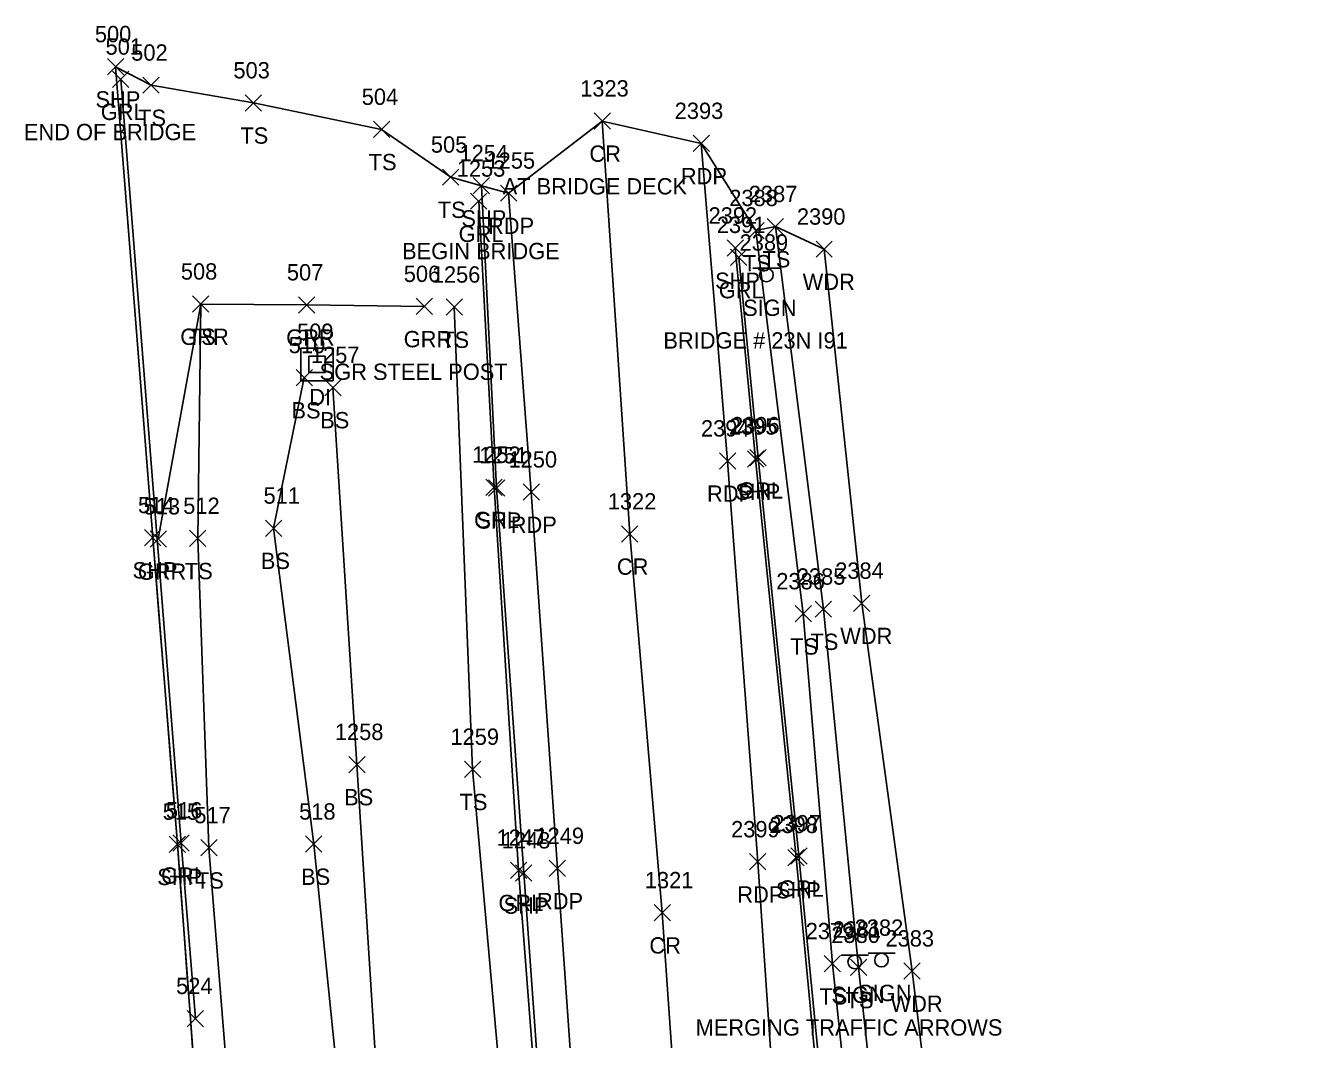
# Model space of a CAD drawing. Extents: x 1650221 to 1650634, y 244606 to 249996.
# Drawn here: x 1650220.8 to 1650378.2, y 247145.3 to 247269.5 of the extents above; entities that cross this region are included whole.
import ezdxf

# ---------------------------------------------------------------- set-up
doc = ezdxf.new("R2010")
doc.units = 0
for name, color, linetype in [('D_A', 7, 'Continuous'), ('D_I', 7, 'Continuous'), ('DS', 7, 'Continuous'), ('L_A', 7, 'Continuous'), ('L_I', 7, 'Continuous'), ('L_TIC', 7, 'Continuous'), ('LAWA', 7, 'Continuous'), ('LELB', 7, 'Continuous'), ('LSOGP', 7, 'Continuous'), ('P_A', 7, 'Continuous'), ('P_C', 7, 'Continuous'), ('P_I', 7, 'Continuous'), ('P_TIC', 7, 'Continuous'), ('PET', 7, 'Continuous'), ('PRC', 7, 'Continuous'), ('PSP', 7, 'Continuous'), ('R_A', 7, 'Continuous'), ('R_C', 7, 'Continuous'), ('R_I', 7, 'Continuous'), ('R_TIC', 7, 'Continuous'), ('RGR', 7, 'Continuous'), ('S_A', 7, 'Continuous'), ('S_C', 7, 'Continuous'), ('S_I', 7, 'Continuous'), ('SSGN', 7, 'Continuous')]:
    doc.layers.add(name, color=color, linetype=linetype)

msp = doc.modelspace()

# ---------------------------------------------------------------- linework, layer by layer
at = {"layer": 'DS'}
for p, q in [((1650254.51, 247229.97), (1650258.51, 247229.97)), ((1650254.51, 247225.97), (1650254.51, 247229.97)), ((1650258.51, 247229.97), (1650258.51, 247225.97)), ((1650255.51, 247226.97), (1650255.51, 247228.97)), ((1650255.51, 247228.97), (1650257.51, 247228.97)), ((1650256.52, 247227.97), (1650256.52, 247227.97)), ((1650256.52, 247227.97), (1650256.52, 247227.97)), ((1650257.51, 247228.97), (1650257.51, 247226.97)), ((1650257.51, 247226.97), (1650255.51, 247226.97)), ((1650258.51, 247225.97), (1650254.51, 247225.97))]:
    msp.add_line(p, q, dxfattribs=at)
at = {"layer": 'L_TIC'}
for points in [[(1650235.19, 247261.18), (1650237.19, 247263.18)], [(1650237.19, 247261.18), (1650235.19, 247263.18)], [(1650247.71, 247259.01), (1650249.71, 247261.01)], [(1650249.71, 247259.01), (1650247.71, 247261.01)], [(1650263.43, 247255.76), (1650265.43, 247257.76)], [(1650265.43, 247255.76), (1650263.43, 247257.76)], [(1650271.9, 247249.91), (1650273.9, 247251.91)], [(1650273.9, 247249.91), (1650271.9, 247251.91)], [(1650309.27, 247243.37), (1650311.27, 247245.37)], [(1650311.27, 247243.37), (1650309.27, 247245.37)], [(1650309.27, 247243.37), (1650311.27, 247245.37)], [(1650311.27, 247243.37), (1650309.27, 247245.37)], [(1650311.67, 247243.86), (1650313.67, 247245.86)], [(1650313.67, 247243.86), (1650311.67, 247245.86)], [(1650317.64, 247241.09), (1650319.64, 247243.09)], [(1650319.64, 247241.09), (1650317.64, 247243.09)], [(1650241.27, 247234.36), (1650243.27, 247236.36)], [(1650243.27, 247234.36), (1650241.27, 247236.36)], [(1650272.32, 247233.99), (1650274.32, 247235.99)], [(1650274.32, 247233.99), (1650272.32, 247235.99)], [(1650253.94, 247225.35), (1650255.94, 247227.35)], [(1650255.94, 247225.35), (1650253.94, 247227.35)], [(1650257.46, 247224.14), (1650259.46, 247226.14)], [(1650259.46, 247224.14), (1650257.46, 247226.14)], [(1650240.91, 247205.66), (1650242.91, 247207.66)], [(1650242.91, 247205.66), (1650240.91, 247207.66)], [(1650250.19, 247206.91), (1650252.19, 247208.91)], [(1650252.19, 247206.91), (1650250.19, 247208.91)], [(1650322.25, 247197.71), (1650324.25, 247199.71)], [(1650324.25, 247197.71), (1650322.25, 247199.71)], [(1650315.08, 247196.42), (1650317.08, 247198.42)], [(1650317.08, 247196.42), (1650315.08, 247198.42)], [(1650317.55, 247196.99), (1650319.55, 247198.99)], [(1650319.55, 247196.99), (1650317.55, 247198.99)], [(1650260.39, 247177.96), (1650262.39, 247179.96)], [(1650262.39, 247177.96), (1650260.39, 247179.96)], [(1650274.56, 247177.37), (1650276.56, 247179.37)], [(1650276.56, 247177.37), (1650274.56, 247179.37)], [(1650242.27, 247167.76), (1650244.27, 247169.76)], [(1650244.27, 247167.76), (1650242.27, 247169.76)], [(1650255.12, 247168.21), (1650257.12, 247170.21)], [(1650257.12, 247168.21), (1650255.12, 247170.21)], [(1650318.65, 247153.56), (1650320.65, 247155.56)], [(1650320.65, 247153.56), (1650318.65, 247155.56)], [(1650321.86, 247153.1), (1650323.86, 247155.1)], [(1650323.86, 247153.1), (1650321.86, 247155.1)], [(1650328.41, 247152.66), (1650330.41, 247154.66)], [(1650330.41, 247152.66), (1650328.41, 247154.66)]]:
    msp.add_lwpolyline(points, dxfattribs=at)
at = {"layer": 'LAWA'}
msp.add_lwpolyline([(1650378.2, 246794.91), (1650374.9, 246794.97), (1650368.73, 246802.01), (1650359.68, 246824.66), (1650349.32, 246871.74), (1650348.02, 246917.21), (1650345.5, 246965.53), (1650341.28, 247016.15), (1650338.12, 247059.96), (1650335.1, 247106.89), (1650329.41, 247153.66), (1650323.25, 247198.71), (1650318.64, 247242.09)], dxfattribs=at)
at = {"layer": 'LELB'}
for points in [[(1650236.19, 247262.18), (1650248.71, 247260.01), (1650264.43, 247256.76), (1650272.9, 247250.91)], [(1650338.12, 247059.96), (1650328.16, 247105.4), (1650322.86, 247154.1), (1650318.55, 247197.99), (1650312.67, 247244.86), (1650310.27, 247244.37)], [(1650352.21, 246793.58), (1650347.7, 246827.18), (1650344.12, 246870.96), (1650340.96, 246916.6), (1650336.85, 246965.3), (1650332.82, 247015.91), (1650329.05, 247059.02), (1650324.85, 247105.51), (1650319.65, 247154.56), (1650316.08, 247197.42), (1650310.27, 247244.37)], [(1650242.27, 247235.36), (1650241.91, 247206.66), (1650243.27, 247168.76), (1650246.51, 247128.17), (1650248.83, 247083.97), (1650252.85, 247030.65), (1650256.86, 246977.49), (1650260.95, 246918.52), (1650265.57, 246863.83), (1650269.89, 246812.16), (1650273.23, 246757.17), (1650276.03, 246723.56), (1650279.21, 246672.89), (1650281.34, 246632.54), (1650285.04, 246583.81), (1650287.41, 246538.25), (1650291.5, 246485.31), (1650295.53, 246435.79), (1650299.48, 246380.33), (1650302.27, 246339.43), (1650306.13, 246294.16), (1650309.79, 246242.03)], [(1650273.32, 247234.99), (1650275.56, 247178.37), (1650280.16, 247126.65), (1650283.32, 247073.18), (1650288.39, 247022.86), (1650291, 246971.3), (1650295.86, 246921.31), (1650299.12, 246867.86), (1650302.48, 246825.54), (1650302.49, 246790.4)], [(1650254.94, 247226.35), (1650251.19, 247207.91), (1650256.12, 247169.21), (1650259.77, 247133.43), (1650260.76, 247116.75), (1650264.32, 247083.63), (1650267.53, 247032.12), (1650271.47, 246976.78), (1650276.33, 246918.79), (1650279.06, 246862.8), (1650283.73, 246813.9), (1650289.01, 246756.82), (1650289.41, 246725.67), (1650289.28, 246672.86), (1650289.57, 246632.6), (1650292.55, 246585.88), (1650294.65, 246538.84), (1650297.54, 246482.61), (1650299.6, 246436.73), (1650304.05, 246378.94), (1650306.26, 246339.81), (1650313.05, 246293.73), (1650316.43, 246243)], [(1650258.46, 247225.14), (1650261.39, 247178.96), (1650264.81, 247125.04), (1650270.68, 247074.02), (1650274.2, 247020.9), (1650277.12, 246971.1), (1650282.14, 246919.24), (1650285.26, 246868.32), (1650288.53, 246824.34), (1650289.93, 246790.87)]]:
    msp.add_lwpolyline(points, dxfattribs=at)
at = {"layer": 'LSOGP'}
msp.add_lwpolyline([(1650335.1, 247106.89), (1650329.41, 247153.66), (1650323.25, 247198.71), (1650318.64, 247242.09), (1650312.67, 247244.86), (1650310.27, 247244.37), (1650303.59, 247255.04), (1650291.45, 247257.79), (1650279.98, 247248.95), (1650276.66, 247249.86), (1650272.9, 247250.91), (1650264.43, 247256.76), (1650248.71, 247260.01), (1650236.19, 247262.18), (1650231.83, 247264.44), (1650232.4, 247257.22), (1650232.97, 247250.01), (1650233.54, 247242.8), (1650234.1, 247235.59), (1650234.67, 247228.38), (1650235.24, 247221.17), (1650235.81, 247213.96), (1650236.38, 247206.75), (1650237.13, 247197.36), (1650237.89, 247187.97), (1650238.65, 247178.58), (1650239.4, 247169.19), (1650239.79, 247163.99), (1650240.18, 247158.78), (1650240.57, 247153.57), (1650240.96, 247148.37), (1650241.35, 247143.16)], dxfattribs=at)
at = {"layer": 'P_TIC'}
for points in [[(1650230.83, 247263.44), (1650232.83, 247265.44)], [(1650232.83, 247263.44), (1650230.83, 247265.44)], [(1650290.45, 247256.79), (1650292.45, 247258.79)], [(1650292.45, 247256.79), (1650290.45, 247258.79)], [(1650302.59, 247254.04), (1650304.59, 247256.04)], [(1650304.59, 247254.04), (1650302.59, 247256.04)], [(1650275.66, 247248.86), (1650277.66, 247250.86)], [(1650277.66, 247248.86), (1650275.66, 247250.86)], [(1650278.98, 247247.95), (1650280.98, 247249.95)], [(1650280.98, 247247.95), (1650278.98, 247249.95)], [(1650306.74, 247241.22), (1650308.74, 247243.22)], [(1650308.74, 247241.22), (1650306.74, 247243.22)], [(1650305.81, 247215.14), (1650307.81, 247217.14)], [(1650307.81, 247215.14), (1650305.81, 247217.14)], [(1650309.23, 247215.37), (1650311.23, 247217.37)], [(1650311.23, 247215.37), (1650309.23, 247217.37)], [(1650277.51, 247211.85), (1650279.51, 247213.85)], [(1650279.51, 247211.85), (1650277.51, 247213.85)], [(1650281.75, 247211.34), (1650283.75, 247213.34)], [(1650283.75, 247211.34), (1650281.75, 247213.34)], [(1650235.38, 247205.75), (1650237.38, 247207.75)], [(1650237.38, 247205.75), (1650235.38, 247207.75)], [(1650293.82, 247206.2), (1650295.82, 247208.2)], [(1650295.82, 247206.2), (1650293.82, 247208.2)], [(1650238.4, 247168.19), (1650240.4, 247170.19)], [(1650240.4, 247168.19), (1650238.4, 247170.19)], [(1650314.19, 247166.56), (1650316.19, 247168.56)], [(1650316.19, 247166.56), (1650314.19, 247168.56)], [(1650280.83, 247164.68), (1650282.83, 247166.68)], [(1650282.83, 247164.68), (1650280.83, 247166.68)], [(1650284.97, 247165.23), (1650286.97, 247167.23)], [(1650286.97, 247165.23), (1650284.97, 247167.23)], [(1650309.51, 247166.04), (1650311.51, 247168.04)], [(1650311.51, 247166.04), (1650309.51, 247168.04)], [(1650297.8, 247159.8), (1650299.8, 247161.8)], [(1650299.8, 247159.8), (1650297.8, 247161.8)]]:
    msp.add_lwpolyline(points, dxfattribs=at)
at = {"layer": 'PET'}
for points in [[(1650303.59, 247255.04), (1650306.81, 247216.14), (1650310.51, 247167.04), (1650313.87, 247117.51), (1650317.79, 247067.14), (1650321.46, 247013.25), (1650325.74, 246955.86), (1650329.2, 246907.19), (1650332.99, 246853.31), (1650336.64, 246798.8), (1650340.79, 246743.67), (1650343.55, 246701.32), (1650346.09, 246667.41)], [(1650353.63, 246221.52), (1650350.67, 246260.72), (1650347.78, 246301.59), (1650344.6, 246348.96), (1650342.99, 246369.43), (1650339.44, 246417.63), (1650336.53, 246459.1), (1650332.81, 246507), (1650329.1, 246556.8), (1650325.84, 246602.52), (1650321.75, 246661.01), (1650317.87, 246717.27), (1650314.55, 246761.47), (1650311.27, 246802.48), (1650308.51, 246843.59), (1650304.95, 246897.23), (1650300.96, 246950.35), (1650297.4, 247001.83), (1650293.63, 247056.22), (1650290.13, 247106.77), (1650285.97, 247166.23), (1650282.75, 247212.34), (1650279.98, 247248.95)]]:
    msp.add_lwpolyline(points, dxfattribs=at)
at = {"layer": 'PRC'}
msp.add_lwpolyline([(1650365.1, 246222.23), (1650362.04, 246265.67), (1650358.21, 246317.53), (1650354.88, 246368.98), (1650350.4, 246428.86), (1650346.57, 246483.13), (1650341.97, 246537.02), (1650338.57, 246591.04), (1650334.55, 246647.32), (1650330.72, 246698.07), (1650326.82, 246753.45), (1650322.93, 246808.73), (1650318.78, 246866.3), (1650315.63, 246915.25), (1650311.69, 246971.18), (1650308.09, 247021.19), (1650305.21, 247068.94), (1650301.6, 247120.36), (1650298.8, 247160.8), (1650294.82, 247207.2), (1650291.45, 247257.79)], dxfattribs=at)
at = {"layer": 'PSP'}
for points in [[(1650231.83, 247264.44), (1650236.38, 247206.75), (1650239.4, 247169.19), (1650242.51, 247127.54), (1650245.5, 247084.02), (1650249.81, 247030.22), (1650253.62, 246978.01), (1650257.98, 246918.58), (1650261.69, 246863.47), (1650265.43, 246811.71), (1650269.36, 246757.46), (1650271.77, 246723.3), (1650275.43, 246673.04), (1650278.75, 246632.2), (1650282.06, 246584.21), (1650285.45, 246538.51), (1650289.06, 246485.48), (1650292.63, 246435.74), (1650296.7, 246380.37), (1650299.48, 246339.42), (1650302.95, 246294.11), (1650306.82, 246242.11)], [(1650349.68, 246222.04), (1650346.67, 246260.34), (1650343.46, 246301.15), (1650340.56, 246349.22), (1650338.99, 246369.3), (1650335.68, 246417.66), (1650332.87, 246458.75), (1650329.36, 246506.58), (1650325.51, 246556.6), (1650322.14, 246602.26), (1650317.67, 246660.67), (1650313.65, 246716.62), (1650310.76, 246760.87), (1650307.66, 246803.03), (1650304.71, 246843.75), (1650300.95, 246897.67), (1650297.16, 246949.75), (1650293.72, 247001.93), (1650289.97, 247055.55), (1650286.03, 247107.65), (1650281.83, 247165.68), (1650278.51, 247212.85), (1650276.66, 247249.86)], [(1650307.74, 247242.22), (1650310.23, 247216.37), (1650315.19, 247167.56), (1650319.94, 247117.42), (1650324.85, 247068), (1650329.68, 247013.47), (1650333.89, 246957.27), (1650337.47, 246907.25), (1650341.57, 246853.3), (1650345.82, 246798.32), (1650349.51, 246744.26), (1650352.38, 246701.38), (1650355.13, 246668.21)]]:
    msp.add_lwpolyline(points, dxfattribs=at)
at = {"layer": 'R_TIC'}
for points in [[(1650231.47, 247261.91), (1650233.47, 247263.91)], [(1650233.47, 247261.91), (1650231.47, 247263.91)], [(1650275.32, 247246.97), (1650277.32, 247248.97)], [(1650277.32, 247246.97), (1650275.32, 247248.97)], [(1650307.18, 247240.07), (1650309.18, 247242.07)], [(1650309.18, 247240.07), (1650307.18, 247242.07)], [(1650241.27, 247234.36), (1650243.27, 247236.36)], [(1650243.27, 247234.36), (1650241.27, 247236.36)], [(1650254.26, 247234.26), (1650256.26, 247236.26)], [(1650256.26, 247234.26), (1650254.26, 247236.26)], [(1650268.64, 247234.07), (1650270.64, 247236.07)], [(1650270.64, 247234.07), (1650268.64, 247236.07)], [(1650309.55, 247215.53), (1650311.55, 247217.53)], [(1650311.55, 247215.53), (1650309.55, 247217.53)], [(1650277.21, 247211.92), (1650279.21, 247213.92)], [(1650279.21, 247211.92), (1650277.21, 247213.92)], [(1650236.07, 247205.59), (1650238.07, 247207.59)], [(1650238.07, 247205.59), (1650236.07, 247207.59)], [(1650238.86, 247168.36), (1650240.86, 247170.36)], [(1650240.86, 247168.36), (1650238.86, 247170.36)], [(1650314.55, 247166.77), (1650316.55, 247168.77)], [(1650316.55, 247166.77), (1650314.55, 247168.77)], [(1650280.2, 247165), (1650282.2, 247167)], [(1650282.2, 247165), (1650280.2, 247167)], [(1650240.61, 247146.84), (1650242.61, 247148.84)], [(1650242.61, 247146.84), (1650240.61, 247148.84)]]:
    msp.add_lwpolyline(points, dxfattribs=at)
at = {"layer": 'RGR'}
for points in [[(1650232.47, 247262.91), (1650239.86, 247169.36), (1650241.61, 247147.84)], [(1650306.3, 246761.34), (1650307.52, 246782.05), (1650307.39, 246800.41), (1650304.06, 246843.7), (1650300.5, 246897.69), (1650296.68, 246949.72), (1650293.23, 247001.96), (1650289.46, 247055.48), (1650285.68, 247107.62), (1650281.2, 247166), (1650278.21, 247212.92), (1650276.32, 247247.97)], [(1650308.18, 247241.07), (1650310.55, 247216.53), (1650315.55, 247167.77), (1650320.43, 247117.51), (1650325.42, 247068.18), (1650330.46, 247013.43), (1650334.74, 246957.48), (1650338.49, 246907.23), (1650342.31, 246853.82), (1650346.19, 246798.3), (1650349.87, 246744.52), (1650353.37, 246701.53), (1650355.68, 246682.24), (1650357.83, 246668.94)], [(1650269.64, 247235.07), (1650255.26, 247235.26), (1650242.27, 247235.36), (1650237.07, 247206.59)]]:
    msp.add_lwpolyline(points, dxfattribs=at)
at = {"layer": 'SSGN'}
for p, q in [((1650309.92, 247239.76), (1650313.26, 247239.76)), ((1650311.57, 247238.93), (1650311.57, 247238.93)), ((1650320.73, 247155.61), (1650324.07, 247155.61)), ((1650324.02, 247155.84), (1650327.35, 247155.84)), ((1650322.38, 247154.77), (1650322.38, 247154.77)), ((1650325.66, 247155), (1650325.66, 247155))]:
    msp.add_line(p, q, dxfattribs=at)
for centre in [(1650311.57, 247238.93), (1650322.38, 247154.77), (1650325.66, 247155)]:
    msp.add_circle(centre, 0.833, dxfattribs=at)

# ---------------------------------------------------------------- texts
at = {"layer": 'D_A'}
msp.add_text('DI', height=2, dxfattribs=at).set_placement((1650255.57, 247222.97))
at = {"layer": 'D_I'}
msp.add_text('509', height=2, dxfattribs=at).set_placement((1650254.07, 247230.97))
at = {"layer": 'L_A'}
for s, p in [('TS', (1650234.6, 247257.18)), ('TS', (1650247.12, 247255.01)), ('TS', (1650262.84, 247251.76)), ('TS', (1650271.31, 247245.91)), ('TS', (1650308.68, 247239.37)), ('TS', (1650308.68, 247239.37)), ('TS', (1650311.08, 247239.86)), ('WDR', (1650316.01, 247237.09)), ('TS', (1650240.68, 247230.36)), ('TS', (1650271.73, 247229.99)), ('BS', (1650253.38, 247221.35)), ('BS', (1650256.9, 247220.14)), ('BS', (1650249.63, 247202.91)), ('TS', (1650240.32, 247201.66)), ('TS', (1650316.96, 247192.99)), ('WDR', (1650320.61, 247193.71)), ('TS', (1650314.49, 247192.42)), ('BS', (1650259.83, 247173.96)), ('TS', (1650273.97, 247173.37)), ('TS', (1650241.68, 247163.76)), ('BS', (1650254.56, 247164.21)), ('TS', (1650318.06, 247149.56)), ('TS', (1650321.27, 247149.1)), ('WDR', (1650326.77, 247148.66))]:
    msp.add_text(s, height=2, dxfattribs=at).set_placement(p)
at = {"layer": 'L_I'}
for s, p in [('502', (1650233.75, 247265.18)), ('503', (1650246.27, 247263.01)), ('504', (1650261.99, 247259.76)), ('505', (1650270.46, 247253.91)), ('2388', (1650307.01, 247247.37)), ('2388', (1650307.01, 247247.37)), ('2387', (1650309.41, 247247.86)), ('2390', (1650315.3, 247245.09)), ('508', (1650239.83, 247238.36)), ('1256', (1650270.57, 247237.99)), ('510', (1650253.05, 247229.35)), ('1257', (1650255.76, 247228.14)), ('511', (1650249.96, 247210.91)), ('512', (1650240.12, 247209.66)), ('2385', (1650315.29, 247200.99)), ('2384', (1650319.99, 247201.71)), ('2386', (1650312.77, 247200.42)), ('1258', (1650258.7, 247181.96)), ('1259', (1650272.86, 247181.37)), ('517', (1650241.48, 247171.76)), ('518', (1650254.32, 247172.21)), ('2379', (1650316.38, 247157.56)), ('2380', (1650319.52, 247157.1)), ('2383', (1650326.15, 247156.66))]:
    msp.add_text(s, height=2, dxfattribs=at).set_placement(p)
at = {"layer": 'P_A'}
for s, p in [('SHP', (1650229.37, 247259.44)), ('CR', (1650289.88, 247252.79)), ('RDP', (1650301.08, 247250.04)), ('SHP', (1650274.2, 247244.86)), ('RDP', (1650277.46, 247243.95)), ('SHP', (1650305.28, 247237.22)), ('RDP', (1650304.29, 247211.14)), ('SHP', (1650307.76, 247211.37)), ('SHP', (1650276.04, 247207.85)), ('RDP', (1650280.24, 247207.34)), ('SHP', (1650233.91, 247201.75)), ('CR', (1650293.25, 247202.2)), ('SHP', (1650236.94, 247164.19)), ('RDP', (1650308, 247162.04)), ('SHP', (1650312.72, 247162.56)), ('SHP', (1650279.37, 247160.68)), ('RDP', (1650283.46, 247161.23)), ('CR', (1650297.23, 247155.8))]:
    msp.add_text(s, height=2, dxfattribs=at).set_placement(p)
at = {"layer": 'P_C'}
for s, p in [('END OF BRIDGE', (1650220.6, 247255.44)), ('AT BRIDGE DECK', (1650279.26, 247248.79)), ('BEGIN BRIDGE', (1650266.93, 247240.86))]:
    msp.add_text(s, height=2, dxfattribs=at).set_placement(p)
at = {"layer": 'P_I'}
for s, p in [('500', (1650229.3, 247267.44)), ('1323', (1650288.75, 247260.79)), ('2393', (1650300.33, 247258.04)), ('1254', (1650273.97, 247252.86)), ('1255', (1650277.28, 247251.95)), ('2392', (1650304.48, 247245.22)), ('2394', (1650303.55, 247219.14)), ('2395', (1650306.97, 247219.37)), ('1251', (1650276.38, 247215.85)), ('1250', (1650279.97, 247215.34)), ('1322', (1650292.13, 247210.2)), ('514', (1650234.58, 247209.75)), ('515', (1650237.61, 247172.19)), ('2399', (1650307.24, 247170.04)), ('2398', (1650311.93, 247170.56)), ('1248', (1650279.14, 247168.68)), ('1249', (1650283.27, 247169.23)), ('1321', (1650296.67, 247163.8))]:
    msp.add_text(s, height=2, dxfattribs=at).set_placement(p)
at = {"layer": 'R_A'}
for s, p in [('GRL', (1650230.02, 247257.91)), ('GRL', (1650273.86, 247242.97)), ('GRL', (1650305.73, 247236.07)), ('GRR', (1650239.76, 247230.36)), ('GRR', (1650252.74, 247230.26)), ('GRR', (1650267.13, 247230.07)), ('GRL', (1650308.1, 247211.53)), ('GRL', (1650275.75, 247207.92)), ('GRR', (1650234.55, 247201.59)), ('GRL', (1650237.4, 247164.36)), ('GRL', (1650313.09, 247162.77)), ('GRL', (1650278.74, 247161))]:
    msp.add_text(s, height=2, dxfattribs=at).set_placement(p)
at = {"layer": 'R_C'}
msp.add_text('SGR STEEL POST', height=2, dxfattribs=at).set_placement((1650256.83, 247226.07))
at = {"layer": 'R_I'}
for s, p in [('501', (1650230.6, 247265.91)), ('1253', (1650273.63, 247250.97)), ('2391', (1650305.49, 247244.07)), ('508', (1650239.83, 247238.36)), ('507', (1650252.82, 247238.26)), ('506', (1650267.14, 247238.07)), ('2396', (1650307.24, 247219.53)), ('1252', (1650275.51, 247215.92)), ('513', (1650235.27, 247209.59)), ('516', (1650238, 247172.36)), ('2397', (1650312.29, 247170.77)), ('1247', (1650278.5, 247169)), ('524', (1650239.25, 247150.84))]:
    msp.add_text(s, height=2, dxfattribs=at).set_placement(p)
at = {"layer": 'S_A'}
for p in [(1650308.71, 247233.91), (1650319.52, 247149.75), (1650322.8, 247149.98)]:
    msp.add_text('SIGN', height=2, dxfattribs=at).set_placement(p)
at = {"layer": 'S_C'}
for s, p in [('BRIDGE # 23N I91', (1650298.94, 247229.91)), ('MERGING TRAFFIC ARROWS', (1650302.89, 247145.75))]:
    msp.add_text(s, height=2, dxfattribs=at).set_placement(p)
at = {"layer": 'S_I'}
for s, p in [('2389', (1650308.28, 247241.91)), ('2381', (1650319.67, 247157.75)), ('2382', (1650322.38, 247157.98))]:
    msp.add_text(s, height=2, dxfattribs=at).set_placement(p)

doc.saveas('drawing.dxf')
